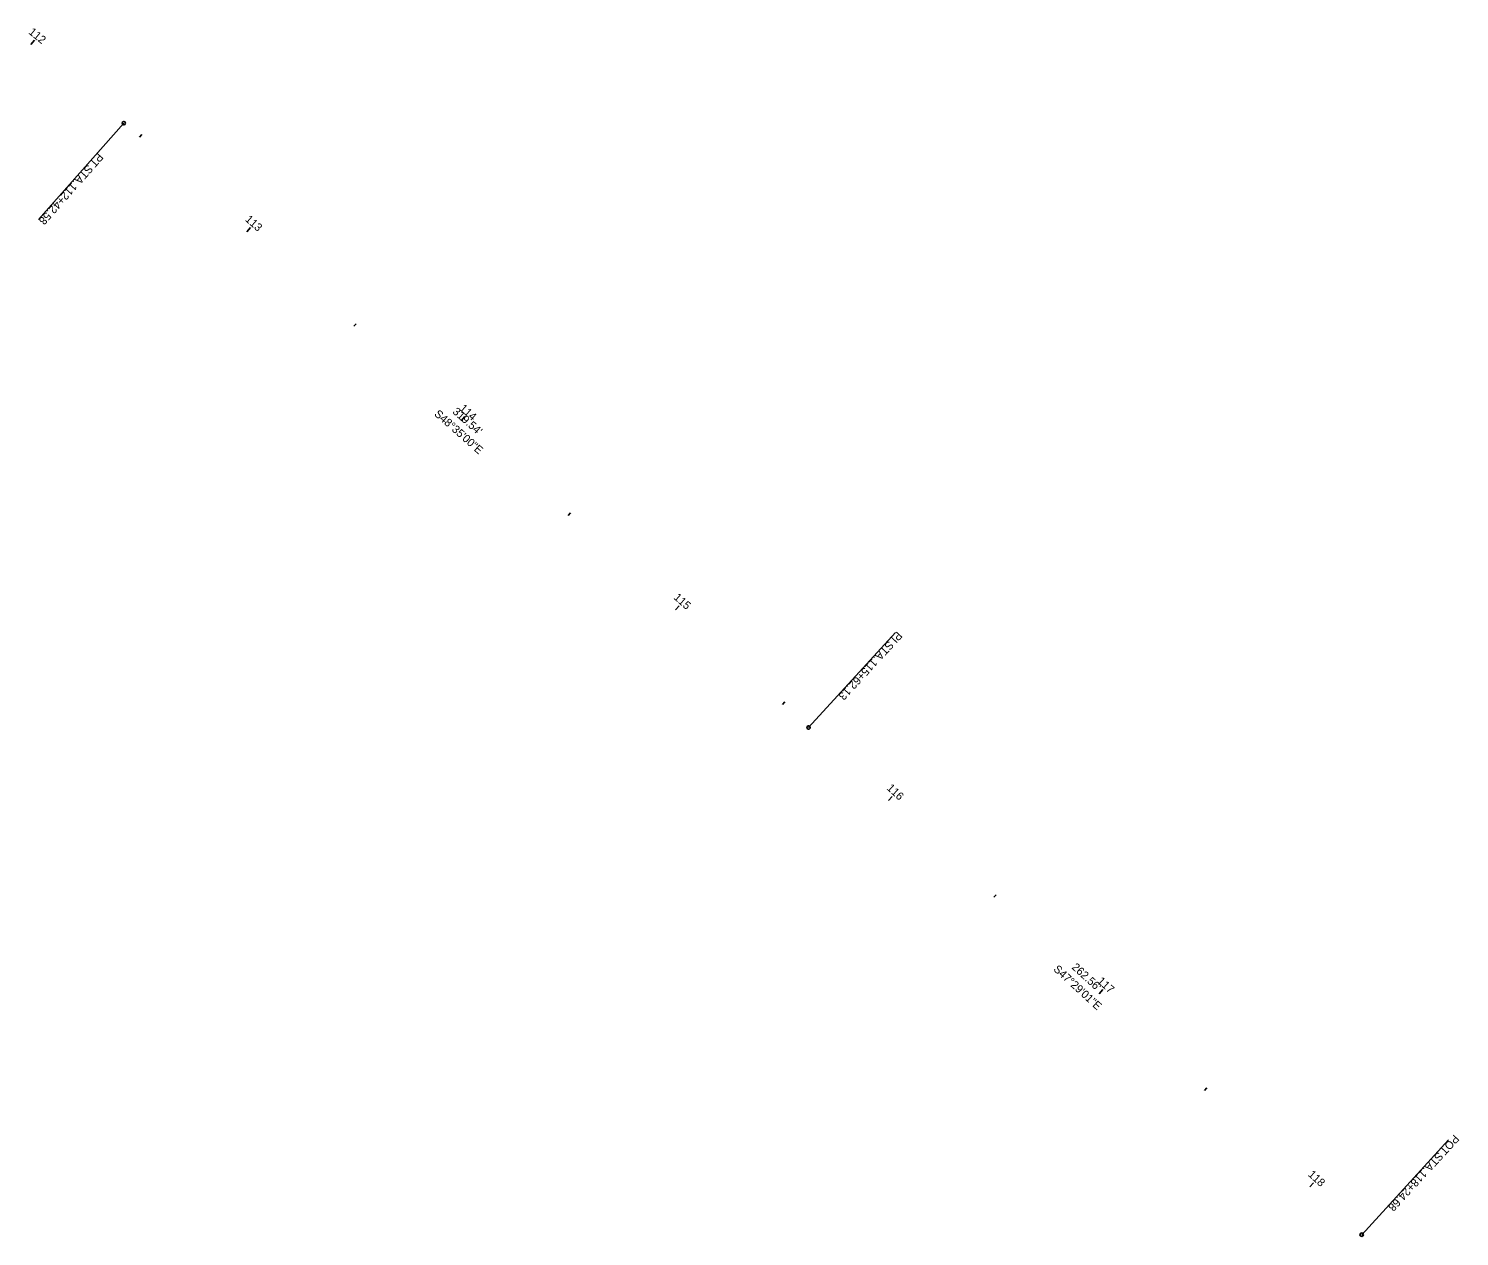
# Model space of a CAD drawing. Extents: x 1600023 to 1602131, y 285824 to 287284.
# Drawn here: x 1601631 to 1602131, y 285824 to 286247 of the extents above; entities that cross this region are included whole.
import ezdxf

# ---------------------------------------------------------------- set-up
doc = ezdxf.new("R2010")
doc.units = 0
for name, color, linetype in [('PM_P_CL_Double_Solid', 7, 'Continuous'), ('PM_P_Dotted_Line', 7, 'Continuous'), ('PM_P_Edge_Line', 7, 'Continuous'), ('PM_P_Transverse_Line', 7, 'Continuous')]:
    doc.layers.add(name, color=color, linetype=linetype)

msp = doc.modelspace()

# ---------------------------------------------------------------- linework, layer by layer
at = {"layer": 'PM_P_CL_Double_Solid'}
for p, q in [((1601664.01, 286213.55), (1601634.24, 286179.8)), ((1601903.64, 286002.16), (1601934.05, 286035.33)), ((1602097.17, 285824.72), (1602127.58, 285857.89))]:
    msp.add_line(p, q, dxfattribs=at)
for centre in [(1601664.01, 286213.55), (1601903.64, 286002.16), (1602097.17, 285824.72)]:
    msp.add_circle(centre, 0.6, dxfattribs=at)
at = {"layer": 'PM_P_Transverse_Line'}
for p, q in [((1601631.48, 286241.03), (1601632.74, 286242.58)), ((1601669.57, 286208.64), (1601670.36, 286209.54)), ((1601707.07, 286175.57), (1601708.39, 286177.06)), ((1601744.56, 286142.49), (1601745.36, 286143.39)), ((1601782.06, 286109.41), (1601783.38, 286110.91)), ((1601819.55, 286076.34), (1601820.35, 286077.24)), ((1601857.05, 286043.26), (1601858.37, 286044.76)), ((1601894.55, 286010.18), (1601895.34, 286011.08)), ((1601931.56, 285976.57), (1601932.91, 285978.04)), ((1601968.41, 285942.78), (1601969.22, 285943.66)), ((1602005.26, 285908.99), (1602006.62, 285910.46)), ((1602042.12, 285875.2), (1602042.93, 285876.08)), ((1602078.97, 285841.41), (1602080.32, 285842.88))]:
    msp.add_line(p, q, dxfattribs=at)

# ---------------------------------------------------------------- texts
at = {"layer": 'PM_P_CL_Double_Solid'}
for s, rotation, p in [('PT', 228.5834, (1601655.04, 286203.32)), (' STA. ', 228.5834, (1601652.12, 286200.01)), ('112+42.58', 228.5834, (1601645.87, 286192.92)), ('PI', 227.4836, (1601934.64, 286035.91)), (' STA. ', 227.4836, (1601932.34, 286033.41)), ('115+62.13', 227.4836, (1601925.96, 286026.44)), ('POT', 227.4836, (1602129.49, 285859.92)), (' STA. ', 227.4836, (1602124.63, 285854.61)), ('118+24.68', 227.4836, (1602118.24, 285847.64))]:
    msp.add_text(s, height=2.8, rotation=rotation, dxfattribs=at).set_placement(p)
at = {"layer": 'PM_P_Dotted_Line'}
for s, rotation, p in [("319.54'", 318.5834, (1601778.84, 286112.3)), ("262.56'", 317.4836, (1601995.51, 285917.99))]:
    msp.add_text(s, height=2.8, rotation=rotation, dxfattribs=at).set_placement(p)
at = {"layer": 'PM_P_Edge_Line'}
for s, rotation, p in [('S48°35\'00"E', 318.5834, (1601772.45, 286111.49)), ('S47°29\'01"E', 317.4836, (1601989.1, 285917.3))]:
    msp.add_text(s, height=2.8, rotation=rotation, dxfattribs=at).set_placement(p)
at = {"layer": 'PM_P_Transverse_Line'}
for s, rotation, p in [('112', 321.0233, (1601630.51, 286245.04)), ('113', 318.5834, (1601706.27, 286179.6)), ('114', 318.5834, (1601781.26, 286113.45)), ('115', 318.5834, (1601856.23, 286047.32)), ('116', 317.4836, (1601930.77, 285980.68)), ('117', 317.4836, (1602004.44, 285913.14)), ('118', 317.4836, (1602078.2, 285845.5))]:
    msp.add_text(s, height=2.8, rotation=rotation, dxfattribs=at).set_placement(p)

doc.saveas('drawing.dxf')
